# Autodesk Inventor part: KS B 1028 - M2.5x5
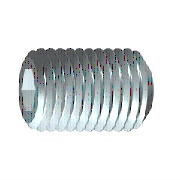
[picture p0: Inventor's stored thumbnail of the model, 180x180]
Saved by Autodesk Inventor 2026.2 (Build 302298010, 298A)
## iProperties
Created: 2025-01
Part Number: KS B 1028 - M2.5x5
Material: 강철, 연강
Description: 6각 소켓 머리 없는 멈춤 나사
Document SubType Name: Modeling
Standard: KS B 1028
Designer: work
Standards Organization: KS
Language: ko-KR
Size Designation: M2.5x5
Categories: <MemberInstance><Categories><Category DisplayName="조임쇠" InternalName="e4da775c-781d-43d5-af7c-5136215cf5a6" Mnemonic="FSTN"><Category DisplayName="볼트" InternalN
Density: 7.85 g/cm^3
Appearance: 반연마
IsCustomPart: 1
Author: work
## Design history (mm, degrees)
revolve "본체" stored, may be unused: angle "d6" = 90 deg
sketch "스케치2"
  geometry: L1 (0.751, 0)-(0.375, -0.65); L2 (0.375, -0.65)-(-0.375, -0.65); L3 (-0.375, -0.65)-(-0.751, 0); L4 (-0.751, 0)-(-0.375, 0.65); L5 (-0.375, 0.65)-(0.375, 0.65); L6 (0.375, 0.65)-(0.751, 0); C1 r 1.25 at (0, 0) reference; A1 r 0.751 centre (0, 0) between (0.751, 0) and (0.375, -0.65) reference; 1 further point
  constraints: 12 end point, 2 point on circle, 1 coincident, 1 horizontal, 11 other
extrude "슬롯" join sketch "스케치2" distance "d8" = 2 (= INTI); taper "d9" = 0 deg
workaxis "Work Axis1"
workplane "Work Plane1"
body "Solid1"
chamfer "모따기1" distance "d10" = 0.65 (= -0.5 x SPD + 0.5 x NND); stored, may be unused: angle "d11" = 45 deg (= FAWI), second distance "d33" = 0.65 (= -0.5 x SPD + 0.5 x NND)
feature "스레드" dims "d14" = 5 (= NLG), "d15" = 0
chamfer "모따기2" distance "d12" = 0.27605 (= -0.5 x GD1 + 0.5 x NND); stored, may be unused: angle "d13" = 45 deg (= FAWI), second distance "d34" = 0.27605 (= -0.5 x GD1 + 0.5 x NND)
sketch "스케치1"
  geometry: L1 (0.346, 0)-(2.567, 0); L2 (5, 0.751)-(5, 1.25); L3 (5, 1.25)-(0, 1.25); L4 (5, 0.751)-(3, 0.751); L5 (3, 0.751)-(2.567, 0); L6 (0, 0.6)-(0.346, 0); L7 (0, -0.25)-(0, 1.5) reference; L8 (0, 0.6)-(0, 1.25); 1 further point
  constraints: 14 end point, 2 parallel, 2 perpendicular, 2 point on line, 1 horizontal
  dimensions: "d0" = 2 distance of L2.start L4.end (= INTI); "d1" = 60 deg angle of L5 L1; "d2" = 2.5 diameter of L3 L1 (= NND); "d3" = 1.50111 diameter of L4 L1 (= 1.1547 x SW); "d4" = 5 distance from line of L2 L6.start (= NLG); "d5" = 60 deg angle of L1 L6 (= 0.5 x ANG); "d7" = 1.2 diameter of L6.start L1 (= SPD)
other parameters: "NND" = 2.5 [user parameter; used in 5 equation terms], "NLG" = 5 [user parameter; used in 2 equation terms], "INTI" = 2 [user parameter; used in 2 equation terms], "FAWI" = 45 deg [user parameter; used in 2 equation terms], "SW" = 1.3 [user parameter; used in 2 equation terms], "GD1" = 1.94789 (= THREADDIA - 1.2269 x PTC) [user parameter; used in 2 equation terms], "ANG" = 120 deg [user parameter; used in 1 equation term], "FAWI1" = 45 deg [user parameter], "SPD" = 1.2 [user parameter; used in 3 equation terms], "d16" = 0, "d35" = 0, "d37" = 0, "GUL" = 0.27605 (= 0.61345 x PTC) [user parameter], "TPU" = 22.22222 (computed from PTC) [user parameter], "TOA" = 30 deg [user parameter], "THREADDIA" = 2.5 [user parameter; used in 1 equation term], "PTC" = 0.45 [user parameter; used in 4 equation terms], "GAL" = 0.27605 (= 0.61345 x PTC) [user parameter], "E0" = 1.5015 (= 1.155 x SW) [user parameter]
